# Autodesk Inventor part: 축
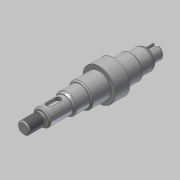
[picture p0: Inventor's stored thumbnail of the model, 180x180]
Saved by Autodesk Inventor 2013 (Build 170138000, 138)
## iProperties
Created: 2019-09
Part Number: 축
Material: 강철, 연강
Document SubType Name: Modeling
Designer: mduedu
Density: 7.86 g/cm^3
Mass: 210.278 g
Surface Area: 69.4764 cm^2
Volume: 26.7529 cm^3
Author: mduedu
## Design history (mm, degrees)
sketch "스케치1"
  geometry: L1 (0, 0)-(15, 0); L2 (15, 0)-(15, 5); L3 (15, 5)-(0, 5); L4 (0, 5)-(0, 0); L5 (15, 0)-(34, 0); L6 (34, 0)-(34, 7); L7 (34, 7)-(15, 7); L8 (15, 7)-(15, 0); L9 (34, 0)-(47, 0); L10 (47, 0)-(47, 8.5); L11 (47, 8.5)-(34, 8.5); L12 (34, 8.5)-(34, 0); L13 (47, 0)-(63, 0); L14 (63, 0)-(63, 10); L15 (63, 10)-(47, 10); L16 (47, 10)-(47, 0); L17 (63, 0)-(75, 0); L18 (75, 0)-(75, 13.5); L19 (75, 13.5)-(63, 13.5); L20 (63, 13.5)-(63, 0); L21 (75, 0)-(90, 0); L22 (90, 0)-(90, 10); L23 (90, 10)-(75, 10); L24 (75, 10)-(75, 0); L25 (90, 0)-(102, 0); L26 (102, 0)-(102, 8.5); L27 (102, 8.5)-(90, 8.5); L28 (90, 8.5)-(90, 0); L29 (102, 0)-(111, 0); L30 (111, 0)-(111, 5.5); L31 (111, 5.5)-(102, 5.5); L32 (102, 5.5)-(102, 0)
  constraints: 64 end point, 16 parallel, 8 horizontal, 8 perpendicular
  dimensions: "d0" = 111 distance between parallel lines of L30 L4; "d2" = 15 distance of L2.end L3.end; "d3" = 19 distance of L6.end L7.end; "d4" = 12 distance of L18.end L19.end; "d5" = 15 distance of L22.end L23.end; "d6" = 12 distance of L26.end L27.end; "d7" = 9 distance of L30.end L31.end; "d8" = 16 distance of L14.end L15.end; "d9" = 10 diameter of L3 L1; "d10" = 14 diameter of L7 L5; "d11" = 17 diameter of L11 L9; "d12" = 20 diameter of L15 L13; "d13" = 27 diameter of L19 L17; "d14" = 20 diameter of L23 L21; "d15" = 17 diameter of L27 L25; "d16" = 11 diameter of L31 L29
revolve "회전1" sketch "스케치1" stored, may be unused: angle "d17" = 90 deg
sketch "스케치2"
  geometry: L1 (0, -5)-(0, 5) reference; L2 (0, 5)-(15, 5) reference; L3 (15, 5)-(15, 7) reference; L4 (15, 7)-(34, 7) reference; L5 (34, 7)-(34, 8.5) reference; L6 (34, 8.5)-(47, 8.5) reference; L7 (47, 8.5)-(47, 10) reference; L8 (47, 10)-(63, 10) reference; L9 (63, 10)-(63, 13.5) reference; L10 (63, 13.5)-(75, 13.5) reference; L11 (75, 13.5)-(75, 10) reference; L12 (75, 10)-(90, 10) reference; L13 (90, 10)-(90, 8.5) reference; L14 (90, 8.5)-(102, 8.5) reference; L15 (102, 8.5)-(102, 5.5) reference; L16 (102, 5.5)-(111, 5.5) reference; L17 (111, 5.5)-(111, -5.5) reference; L18 (111, -5.5)-(102, -5.5) reference; L19 (102, -5.5)-(102, -8.5) reference; L20 (102, -8.5)-(90, -8.5) reference; L21 (90, -8.5)-(90, -10) reference; L22 (90, -10)-(75, -10) reference; L23 (75, -10)-(75, -13.5) reference; L24 (75, -13.5)-(63, -13.5) reference; L25 (63, -13.5)-(63, -10) reference; L26 (63, -10)-(47, -10) reference; L27 (47, -10)-(47, -8.5) reference; L28 (47, -8.5)-(34, -8.5) reference; L29 (34, -8.5)-(34, -7) reference; L30 (34, -7)-(15, -7) reference; L31 (15, -7)-(15, -5) reference; L32 (15, -5)-(0, -5) reference; L33 (0, 0)-(111, 0); L34 (15, 5)-(12.014, 5); L35 (13.4, 4.2)-(15, 4.2); L36 (15, 4.2)-(15, 5); L37 (12.014, 5)-(13.4, 4.2)
  constraints: 10 end point, 1 horizontal, 1 midpoint, 1 parallel, 1 vertical
  dimensions: "d18" = 30 deg angle of L2 L37; "d19" = 8.4 diameter of L35 L33; "d21" = 2.986 distance from line of L34.end L36
revolve "회전2" sketch "스케치2" stored, may be unused: angle "d22" = 90 deg
fillet "모깎기1" dims "d23" = 0.6
feature "스레드1" dims "d24" = 10, "d25" = 0
chamfer "모따기1" distance "d26" = 1; stored, may be unused: second distance "d27" = 2, angle "d28" = 45 deg
chamfer "모따기2" distance "d29" = 1; stored, may be unused: second distance "d30" = 2, angle "d31" = 45 deg
chamfer "모따기3" distance "d32" = 1.819; stored, may be unused: second distance "d33" = 2, angle "d34" = 30 deg
fillet "모깎기2" dims "d35" = 2
chamfer "모따기4" distance "d36" = 1; stored, may be unused: second distance "d37" = 2, angle "d38" = 30 deg
fillet "모깎기3" dims "d39" = 0.3
chamfer "모따기5" distance "d40" = 1; stored, may be unused: second distance "d41" = 2, angle "d42" = 30 deg
chamfer "모따기6" distance "d43" = 1.819; stored, may be unused: second distance "d44" = 2, angle "d45" = 30 deg
chamfer "모따기7" distance "d46" = 0.5; stored, may be unused: second distance "d47" = 2, angle "d48" = 30 deg
fillet "모깎기4" dims "d49" = 2
node "작업 평면1"
sketch "스케치3" dims "d51" = 12
  geometry: L1 (3, -2.5)-(-4, -2.5); L2 (-4, -2.5)-(-4, 2.5); L3 (-4, 2.5)-(3, 2.5); L4 (3, 2.5)-(3, -2.5); L5 (-9.5, 7.45)-(-9.5, -7.45) reference; 3 further points
  constraints: 8 end point, 2 midpoint, 2 parallel, 2 vertical alignment, 1 horizontal, 1 horizontal alignment, 1 perpendicular, 4 other
  dimensions: "d50" = 3 dimension on L5; "d52" = 5 distance between parallel lines of L3 L1
extrude "돌출1" cut sketch "스케치3" distance "d53" = 3; taper "d54" = 0 deg
node "작업 평면3"
sketch "스케치4"
  geometry: L1 (-4.5, -5)-(-4.5, 5) reference; L2 (-4.5, -2)-(1.5, -2); L3 (1.5, -2)-(1.5, 2); L4 (1.5, 2)-(-4.5, 2); L5 (-4.5, 2)-(-4.5, -2); 3 further points
  constraints: 8 end point, 2 horizontal alignment, 2 midpoint, 2 parallel, 1 horizontal, 1 perpendicular, 1 point on line, 1 vertical alignment, 2 other
  dimensions: "d55" = 4 distance between parallel lines of L4 L2; "d57" = 8 dimension on L1
extrude "돌출2" cut sketch "스케치4" distance "d58" = 2.5; taper "d59" = 0 deg
sketch "스케치5"
  geometry: A1 r 5.5 centre (2, -3) between (0, 2.123) and (4, 2.123) reference; 2 further points
  constraints: 1 point on circle
hole "구멍1" sketch "스케치5" at (2, -8.5) diameter "d60" = 2.459; stored, may be unused: countersink angle "d64" = 90 deg, drill point angle "d66" = 118 deg; dims "d61" = 6, "d62" = 4, "d63" = 2, "d65" = 5
node "솔리드1"
node "절단 모서리 투영1"
